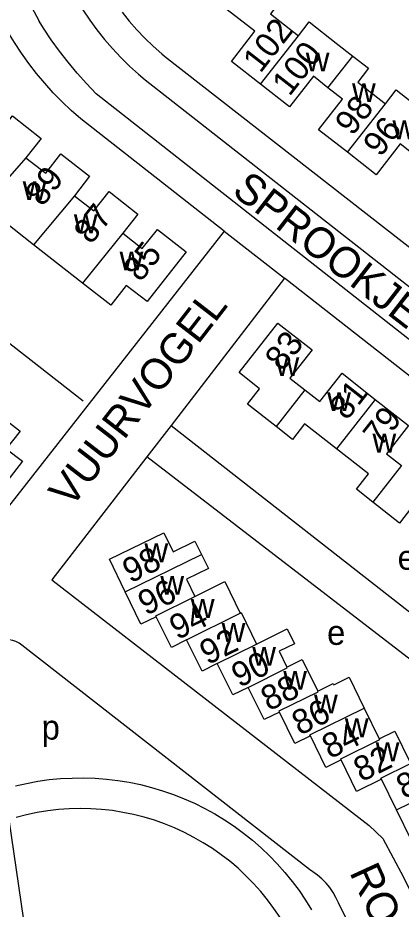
# Model space of a CAD drawing. Extents: x 159441 to 162086, y 388175 to 389787.
# Drawn here: x 161490.5 to 161552.9, y 388825.6 to 388970.9 of the extents above; entities that cross this region are included whole.
import ezdxf

# ---------------------------------------------------------------- set-up
doc = ezdxf.new("R2010")
doc.units = 0
for name, color, linetype in [('BLT_Basislijn', 7, 'Continuous'), ('BLT_Bebouwing', 7, 'Continuous'), ('BLT_Centroide', 7, 'Continuous'), ('BLT_Huisnummer', 7, 'Continuous'), ('BLT_Huisnummer_ tussenligend', 7, 'Continuous'), ('BLT_Onderverdeling_panden', 7, 'Continuous'), ('BLT_Straatnaam', 7, 'Continuous'), ('BLT_Vlakafsluiter', 7, 'Continuous')]:
    doc.layers.add(name, color=color, linetype=linetype)

msp = doc.modelspace()

# ---------------------------------------------------------------- linework, layer by layer
at = {"layer": 'BLT_Basislijn'}
for p, q in [((161488.48, 388980.54), (161493.94, 388970.29)), ((161507.44, 388971.77), (161508.62, 388970.3)), ((161508.62, 388970.3), (161509.86, 388968.88)), ((161509.86, 388968.88), (161511.16, 388967.52)), ((161511.16, 388967.52), (161512.52, 388966.22)), ((161512.52, 388966.22), (161513.93, 388964.97)), ((161513.93, 388964.97), (161514.38, 388964.59)), ((161514.38, 388964.59), (161611.09, 388889.09)), ((161511.2, 388960.73), (161602.59, 388889.14)), ((161598.66, 388883.44), (161503.23, 388958.49)), ((161524.08, 388936.1), (161500.72, 388954.39)), ((161464.67, 388936.85), (161501.08, 388908.43)), ((161533.92, 388928.4), (161515.42, 388904.41)), ((161515.42, 388904.41), (161511.5, 388899.32))]:
    msp.add_line(p, q, dxfattribs=at)
for points in [[(161500.72, 388954.39), (161499.17, 388955.75), (161497.67, 388957.17), (161496.22, 388958.65), (161494.84, 388960.18), (161493.51, 388961.77), (161492.24, 388963.41), (161491.05, 388965.09), (161489.91, 388966.82), (161488.85, 388968.59), (161487.85, 388970.4), (161486.88, 388972.34)], [(161501.07, 388972.14), (161502.18, 388970.49), (161503.35, 388968.89), (161504.58, 388967.33), (161505.88, 388965.83), (161507.24, 388964.38), (161508.65, 388962.99), (161510.12, 388961.65), (161511.2, 388960.73)], [(161503.23, 388958.49), (161501.64, 388960.14), (161500.12, 388961.84), (161498.66, 388963.6), (161497.25, 388965.41), (161495.92, 388967.26), (161494.65, 388969.17), (161493.94, 388970.29)], [(161524.08, 388936.1), (161485.17, 388886.41), (161442.62, 388919.82), (161424.94, 388956.68)], [(161612.46, 388851.77), (161602.53, 388871.82), (161601.69, 388873.18), (161600.79, 388874.5), (161599.81, 388875.77), (161598.78, 388876.99), (161597.69, 388878.15), (161596.54, 388879.26), (161595.34, 388880.31), (161594.56, 388880.93), (161533.92, 388928.4)], [(161515.42, 388904.41), (161575.23, 388857.65), (161582.86, 388842.46)], [(161511.5, 388899.32), (161496.01, 388879.23), (161547.71, 388839.22), (161549.93, 388837.08), (161553.27, 388830.79), (161557.15, 388822.83)], [(161576.81, 388841.19), (161570.62, 388853.78), (161511.5, 388899.32)], [(161546.37, 388819.08), (161542.67, 388826.63), (161542.27, 388827.49), (161541.8, 388828.31), (161541.26, 388829.09), (161540.66, 388829.82), (161539.99, 388830.5), (161539.28, 388831.12), (161538.51, 388831.68), (161537.98, 388832.01), (161491.12, 388868.62), (161490.66, 388868.94), (161490.16, 388869.18), (161489.63, 388869.36), (161489.08, 388869.45), (161488.52, 388869.47), (161487.97, 388869.4), (161487.43, 388869.26), (161486.92, 388869.04), (161486.44, 388868.75), (161486.01, 388868.4), (161485.64, 388867.99), (161485.37, 388867.59), (161485.08, 388867.23)], [(161490.07, 388845.67), (161491.89, 388846.08), (161493.73, 388846.42), (161495.58, 388846.68), (161497.44, 388846.86), (161499.31, 388846.95), (161501.17, 388846.97), (161503.04, 388846.91), (161504.9, 388846.77), (161506.76, 388846.55), (161508.6, 388846.25), (161510.43, 388845.87), (161512.24, 388845.41), (161514.04, 388844.88), (161515.8, 388844.27), (161517.54, 388843.58), (161519.25, 388842.83), (161520.92, 388841.99), (161522.56, 388841.09), (161524.15, 388840.12), (161525.71, 388839.08), (161527.21, 388837.98), (161528.67, 388836.81), (161530.08, 388835.58), (161531.43, 388834.29), (161532.73, 388832.95), (161533.97, 388831.55), (161535.15, 388830.1), (161536.26, 388828.6), (161537.31, 388827.05), (161538.29, 388825.46)], [(161533.17, 388824.24), (161532.18, 388825.7), (161531.14, 388827.11), (161530.02, 388828.47), (161528.85, 388829.78), (161527.62, 388831.03), (161526.33, 388832.23), (161524.99, 388833.37), (161523.6, 388834.44), (161522.16, 388835.45), (161520.67, 388836.4), (161519.15, 388837.27), (161517.59, 388838.08), (161515.99, 388838.81), (161514.36, 388839.47), (161512.7, 388840.06), (161511.02, 388840.57), (161509.31, 388841), (161507.59, 388841.35), (161505.86, 388841.63), (161504.11, 388841.82), (161502.35, 388841.94), (161500.6, 388841.98), (161498.84, 388841.93), (161497.08, 388841.81), (161495.34, 388841.61), (161493.6, 388841.32), (161491.88, 388840.96), (161490.18, 388840.52)], [(161489.01, 388840.17), (161495.27, 388796.95)]]:
    msp.add_lwpolyline(points, dxfattribs=at)
at = {"layer": 'BLT_Bebouwing'}
for points in [[(161529.82, 388979.47), (161532.65, 388977.12), (161531.27, 388975.36), (161533.37, 388973.72), (161531.62, 388971.48), (161536.17, 388967.93)], [(161529.98, 388960.03), (161525.26, 388963.73), (161529.07, 388968.68), (161521.27, 388974.74)], [(161536.17, 388967.93), (161537.89, 388970.18), (161542.33, 388966.71), (161545.05, 388964.59)], [(161545.05, 388964.59), (161547.57, 388962.63), (161545.82, 388960.39), (161550.34, 388956.86)], [(161540.97, 388959.46), (161538.61, 388961.33), (161534.7, 388956.33), (161529.98, 388960.03)], [(161544.14, 388948.93), (161539.43, 388952.62), (161543.33, 388957.58), (161540.97, 388959.46)], [(161550.34, 388956.86), (161552.09, 388959.09), (161559.15, 388953.58)], [(161485.07, 388956.24), (161487.21, 388951.85), (161489.57, 388954.85), (161494.26, 388951.19), (161491.79, 388948.04)], [(161555.12, 388948.43), (161552.74, 388950.29), (161548.85, 388945.24), (161544.14, 388948.93)], [(161491.79, 388948.04), (161495, 388945.52), (161497.47, 388948.68), (161502.13, 388945.03), (161499.7, 388941.83)], [(161493.02, 388933.87), (161489.85, 388936.36), (161485.13, 388940.06), (161487.65, 388943.29)], [(161499.7, 388941.83), (161502.86, 388939.38), (161505.33, 388942.53), (161510.01, 388938.87), (161507.54, 388935.74)], [(161507.54, 388935.74), (161510.73, 388933.23), (161513.2, 388936.37), (161517.87, 388932.72), (161511.53, 388924.59), (161508.12, 388927.25), (161505.6, 388924.02), (161501, 388927.62)], [(161501, 388927.62), (161493.02, 388933.87)], [(161532.52, 388904.24), (161527.86, 388907.89), (161529.83, 388910.39), (161526.5, 388913.02), (161532.83, 388921.1), (161538.38, 388916.73), (161534.77, 388912.12), (161537.2, 388910.22)], [(161537.2, 388910.22), (161539.64, 388908.31), (161543.29, 388912.91), (161548.69, 388908.65)], [(161548.69, 388908.65), (161554.1, 388904.38), (161550.51, 388899.8), (161552.96, 388897.88)], [(161486.59, 388902.16), (161488.83, 388905.05), (161490.82, 388903.49), (161488.56, 388900.61), (161491.23, 388898.58), (161485.32, 388890.97), (161480.68, 388894.59)], [(161542.36, 388900.61), (161537.18, 388904.65), (161535.21, 388902.12), (161532.52, 388904.24)], [(161548.28, 388891.91), (161545.6, 388894.01), (161547.57, 388896.54), (161542.36, 388900.61)], [(161558.12, 388888.26), (161554.59, 388891.03), (161552.62, 388888.51), (161548.28, 388891.91)], [(161507.95, 388877.32), (161505.37, 388882.62), (161514.23, 388886.93), (161515.75, 388883.83), (161519.3, 388885.57), (161520.37, 388883.4)], [(161520.37, 388883.4), (161521.5, 388881.09), (161517.94, 388879.34), (161519.31, 388876.56)], [(161519.31, 388876.56), (161524.18, 388878.98), (161526.7, 388873.84)], [(161513.02, 388873.23), (161510.52, 388872.01), (161507.95, 388877.32)], [(161517.94, 388869.47), (161515.47, 388868.24), (161513.02, 388873.23)], [(161526.7, 388873.84), (161526.83, 388873.9), (161529.33, 388868.78)], [(161529.33, 388868.78), (161534.33, 388871.28), (161535.53, 388868.83), (161533.01, 388867.6), (161534.28, 388865.02)], [(161522.95, 388865.6), (161520.48, 388864.36), (161517.94, 388869.47)], [(161534.28, 388865.02), (161536.8, 388866.26), (161539.31, 388861.13)], [(161527.96, 388861.71), (161525.49, 388860.48), (161522.95, 388865.6)], [(161539.31, 388861.13), (161541.82, 388862.36), (161541.93, 388862.13), (161544.45, 388863.37), (161546.9, 388858.35)], [(161533.1, 388857.7), (161530.56, 388856.46), (161527.96, 388861.71)], [(161538.12, 388853.81), (161535.59, 388852.58), (161533.1, 388857.7)], [(161546.9, 388858.35), (161549.34, 388853.36)], [(161549.34, 388853.36), (161551.85, 388854.59), (161554.35, 388849.47)], [(161543.13, 388849.91), (161540.61, 388848.68), (161538.12, 388853.81)], [(161549.67, 388846.76), (161545.63, 388844.77), (161543.13, 388849.91)], [(161552.13, 388841.75), (161549.67, 388846.76)], [(161554.58, 388836.75), (161552.13, 388841.75)]]:
    msp.add_lwpolyline(points, dxfattribs=at)
at = {"layer": 'BLT_Onderverdeling_panden'}
for p, q in [((161529.98, 388960.03), (161536.17, 388967.93)), ((161540.97, 388959.46), (161545.05, 388964.59)), ((161544.14, 388948.93), (161550.34, 388956.86)), ((161491.79, 388948.04), (161487.65, 388943.29)), ((161499.7, 388941.83), (161493.02, 388933.87)), ((161507.54, 388935.74), (161501, 388927.62)), ((161537.2, 388910.22), (161532.52, 388904.24)), ((161548.69, 388908.65), (161542.36, 388900.61)), ((161552.96, 388897.88), (161548.28, 388891.91)), ((161507.95, 388877.32), (161520.37, 388883.4)), ((161517.94, 388869.47), (161526.7, 388873.84)), ((161522.95, 388865.6), (161529.33, 388868.78)), ((161552.13, 388841.75), (161561, 388846.1))]:
    msp.add_line(p, q, dxfattribs=at)
for points in [[(161513.02, 388873.23), (161512.95, 388873.37), (161519.31, 388876.56)], [(161527.96, 388861.71), (161534.35, 388864.88), (161534.28, 388865.02)], [(161533.1, 388857.7), (161533.01, 388857.89), (161539.38, 388860.99), (161539.31, 388861.13)], [(161538.12, 388853.81), (161538.05, 388853.96), (161546.9, 388858.35)], [(161543.13, 388849.91), (161543.05, 388850.05), (161549.41, 388853.22), (161549.34, 388853.36)], [(161549.67, 388846.76), (161549.6, 388846.9), (161554.42, 388849.33), (161554.35, 388849.47)]]:
    msp.add_lwpolyline(points, dxfattribs=at)
at = {"layer": 'BLT_Vlakafsluiter'}
msp.add_line((161524.08, 388936.1), (161533.92, 388928.4), dxfattribs=at)

# ---------------------------------------------------------------- texts
at = {"layer": 'BLT_Centroide'}
for s, p in [('w', (161537.36, 388962.12)), ('w', (161544.89, 388957.12)), ('w', (161551.48, 388951.06)), ('w', (161491.26, 388941.14)), ('w', (161499.59, 388935.75)), ('w', (161507.04, 388929.67)), ('w', (161532.44, 388912.45)), ('w', (161540.85, 388906.75)), ('w', (161548.23, 388900)), ('w', (161511.09, 388882.12)), ('e', (161552.32, 388880.89)), ('w', (161513.68, 388876.81)), ('w', (161518.64, 388873.03)), ('w', (161523.66, 388869.12)), ('e', (161540.83, 388868.65)), ('w', (161528.65, 388865.25)), ('w', (161533.69, 388861.34)), ('w', (161538.71, 388857.47)), ('p', (161494.34, 388853.21)), ('w', (161543.73, 388853.59)), ('w', (161548.75, 388849.69))]:
    msp.add_text(s, height=4, dxfattribs=at).set_placement(p)
at = {"layer": 'BLT_Huisnummer'}
for s, rotation, p in [('102', 52.1058, (161529.97, 388961.69)), ('98', 52.1058, (161544.96, 388951.46)), ('89', 52.0275, (161494.48, 388939.92)), ('85', 52.0275, (161510.46, 388927.63)), ('83', 51.9779, (161533.54, 388913.07)), ('98', 26.0871, (161508.79, 388878.63)), ('94', 26.0871, (161516.43, 388869.4)), ('90', 26.0871, (161526.53, 388861.61)), ('86', 26.0871, (161536.37, 388853.82)), ('82', 26.0871, (161546.42, 388846.24))]:
    msp.add_text(s, height=4, rotation=rotation, dxfattribs=at).set_placement(p)
at = {"layer": 'BLT_Huisnummer_ tussenligend'}
for s, rotation, p in [('100', 52.1058, (161534.71, 388957.92)), ('96', 52.1058, (161549.54, 388948.01)), ('87', 52.0275, (161502.4, 388933.77)), ('81', 51.9779, (161544.06, 388905.09)), ('79', 51.9779, (161549.52, 388900.77)), ('96', 26.0871, (161511.31, 388873.36)), ('92', 26.0871, (161521.36, 388865.31)), ('88', 26.0871, (161531.32, 388857.79)), ('84', 26.0871, (161541.28, 388849.99)), ('80', 26.0871, (161553.37, 388843.44))]:
    msp.add_text(s, height=4, rotation=rotation, dxfattribs=at).set_placement(p)
at = {"layer": 'BLT_Straatnaam'}
for s, height, rotation, p in [('SPROOKJESBOSCH', 4.9999, 322.2797, (161525.14, 388942.22)), ('VUURVOGEL', 5, 52.2547, (161499.12, 388890.76)), ('ROODKAPJE', 5, 294.6089, (161544.41, 388831.59))]:
    msp.add_text(s, height=height, rotation=rotation, dxfattribs=at).set_placement(p)

doc.saveas('drawing.dxf')
